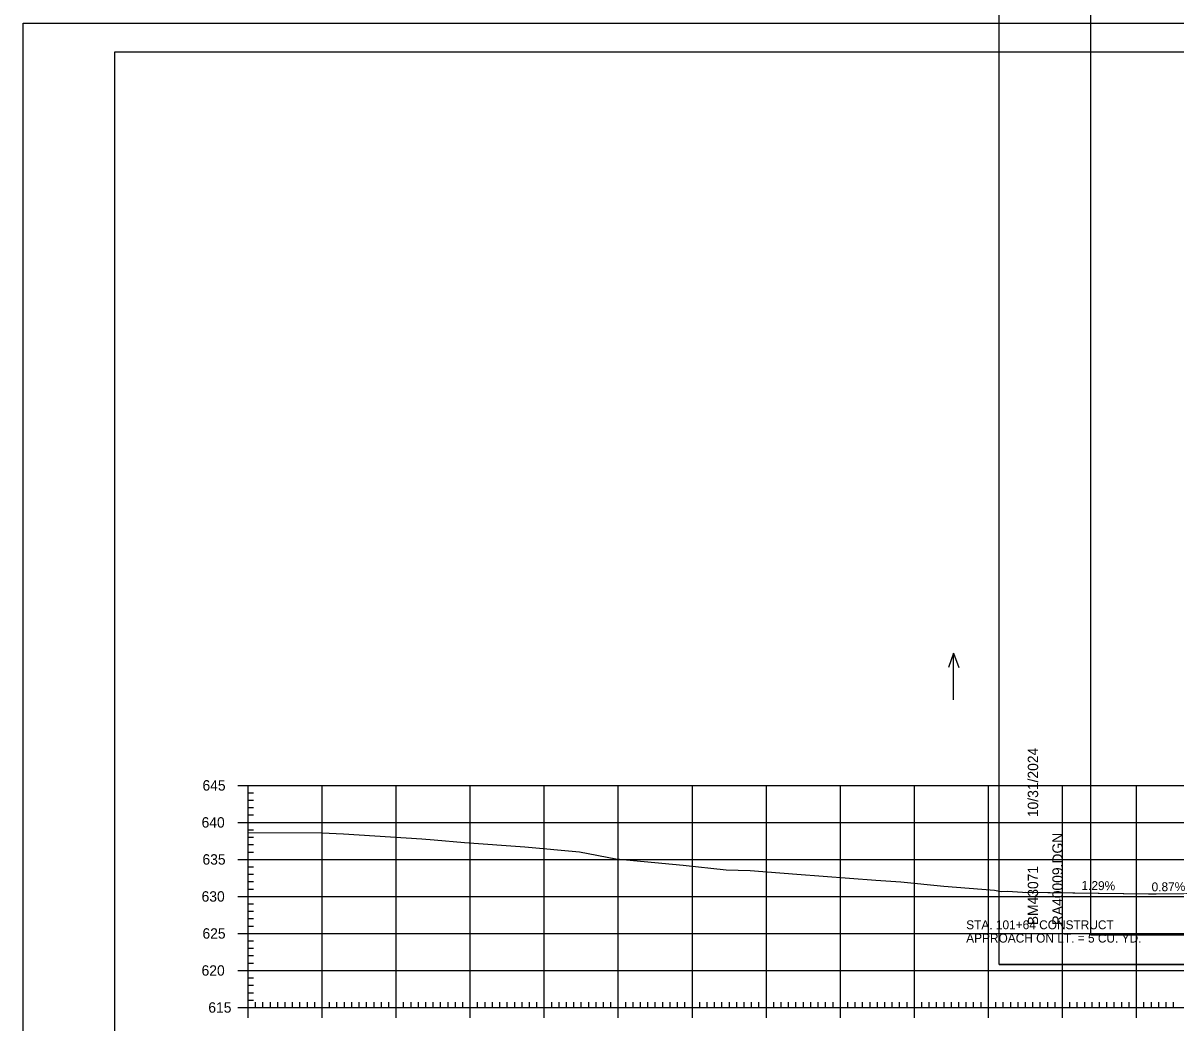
# Model space of a CAD drawing. Extents: x 1381471 to 1382703, y 370300 to 371487.
# Drawn here: x 1381834.4 to 1381990.1, y 370412.6 to 370547.6 of the extents above; entities that cross this region are included whole.
import ezdxf

# ---------------------------------------------------------------- set-up
doc = ezdxf.new("R2010")
doc.units = 0
for name, color, linetype in [('Level 16', 7, 'Continuous'), ('Level 18', 7, 'Continuous'), ('Level 22', 7, 'Continuous'), ('Level 26', 7, 'Continuous'), ('Level 4', 7, 'Continuous'), ('Level 40', 7, 'Continuous'), ('Level 41', 7, 'Continuous'), ('Level 44', 7, 'Continuous'), ('Level 45', 7, 'Continuous'), ('Level 5', 7, 'Continuous'), ('Level 6', 7, 'Continuous')]:
    doc.layers.add(name, color=color, linetype=linetype)

msp = doc.modelspace()

# ---------------------------------------------------------------- linework, layer by layer
at = {"layer": 'Level 16'}
msp.add_line((1381969.77, 370430.24), (1381986.4, 370430.03), dxfattribs=at)
msp.add_lwpolyline([(1381986.4, 370430.03), (1381991.53, 370430.07), (1381991.98, 370430.06), (1381992.77, 370430.05)], dxfattribs=at)
at = {"layer": 'Level 18'}
msp.add_lwpolyline([(1381864.77, 370438.29), (1381874.71, 370438.27), (1381877.66, 370438.13), (1381888.24, 370437.46), (1381889.89, 370437.29), (1381893.98, 370436.94), (1381902.13, 370436.35), (1381909.52, 370435.68), (1381914.45, 370434.75), (1381923.51, 370433.88), (1381929.32, 370433.24), (1381932.59, 370433.16), (1381938.87, 370432.68), (1381949.55, 370431.85), (1381952.95, 370431.62), (1381958.75, 370431.05), (1381965.57, 370430.49), (1381966.49, 370430.33), (1381967.36, 370430.35), (1381969.38, 370430.25), (1381986.4, 370430.03), (1381987.11, 370430.02), (1381987.42, 370430.02), (1381991.53, 370430.07)], dxfattribs=at)
at = {"layer": 'Level 22'}
for p, q in [((1381864.77, 370444.66), (1382144.77, 370444.66)), ((1381864.77, 370414.66), (1381864.77, 370444.66)), ((1381874.77, 370414.66), (1381874.77, 370444.66)), ((1381884.77, 370414.66), (1381884.77, 370444.66)), ((1381894.77, 370414.66), (1381894.77, 370444.66)), ((1381904.77, 370414.66), (1381904.77, 370444.66)), ((1381914.77, 370414.66), (1381914.77, 370444.66)), ((1381924.77, 370414.66), (1381924.77, 370444.66)), ((1381934.77, 370414.66), (1381934.77, 370444.66)), ((1381944.77, 370414.66), (1381944.77, 370444.66)), ((1381954.77, 370414.66), (1381954.77, 370444.66)), ((1381964.77, 370414.66), (1381964.77, 370444.66)), ((1381974.77, 370414.66), (1381974.77, 370444.66)), ((1381984.77, 370414.66), (1381984.77, 370444.66)), ((1381864.77, 370439.66), (1382144.77, 370439.66)), ((1381864.77, 370434.66), (1382144.77, 370434.66)), ((1381864.77, 370429.66), (1382144.77, 370429.66)), ((1381864.77, 370424.66), (1382144.77, 370424.66)), ((1381864.77, 370419.66), (1382144.77, 370419.66)), ((1381864.77, 370414.66), (1382144.77, 370414.66))]:
    msp.add_line(p, q, dxfattribs=at)
at = {"layer": 'Level 26'}
msp.add_line((1381834.37, 370547.63), (1382167.7, 370547.63), dxfattribs=at)
for points in [[(1381834.36, 370547.63), (1382167.7, 370547.63), (1382167.7, 370334.29), (1381834.36, 370334.29)], [(1382080.69, 370543.73), (1382100.31, 370543.73), (1382100.31, 370533.85), (1382116.42, 370533.85), (1382139.62, 370533.85), (1382139.62, 370501.18), (1382162.83, 370501.18), (1382162.95, 370338.27), (1381846.77, 370338.27), (1381846.77, 370543.73)]]:
    msp.add_lwpolyline(points, close=True, dxfattribs=at)
at = {"layer": 'Level 4'}
for p, q in [((1381863.37, 370444.66), (1381866.17, 370444.66)), ((1381864.77, 370414.66), (1381864.77, 370444.66)), ((1381864.77, 370443.66), (1381865.47, 370443.66)), ((1381864.77, 370442.66), (1381865.47, 370442.66)), ((1381864.77, 370441.66), (1381865.47, 370441.66)), ((1381864.77, 370440.66), (1381865.47, 370440.66)), ((1381863.37, 370439.66), (1381866.17, 370439.66)), ((1381864.77, 370438.66), (1381865.47, 370438.66)), ((1381864.77, 370437.66), (1381865.47, 370437.66)), ((1381864.77, 370436.66), (1381865.47, 370436.66)), ((1381863.37, 370434.66), (1381866.17, 370434.66)), ((1381864.77, 370435.66), (1381865.47, 370435.66)), ((1381864.77, 370433.66), (1381865.47, 370433.66)), ((1381864.77, 370432.66), (1381865.47, 370432.66)), ((1381864.77, 370431.66), (1381865.47, 370431.66)), ((1381863.37, 370429.66), (1381866.17, 370429.66)), ((1381864.77, 370430.66), (1381865.47, 370430.66)), ((1381864.77, 370428.66), (1381865.47, 370428.66)), ((1381864.77, 370427.66), (1381865.47, 370427.66)), ((1381864.77, 370426.66), (1381865.47, 370426.66)), ((1381864.77, 370425.66), (1381865.47, 370425.66)), ((1381863.37, 370424.66), (1381866.17, 370424.66)), ((1381864.77, 370423.66), (1381865.47, 370423.66)), ((1381864.77, 370422.66), (1381865.47, 370422.66)), ((1381864.77, 370421.66), (1381865.47, 370421.66)), ((1381864.77, 370420.66), (1381865.47, 370420.66)), ((1381863.37, 370419.66), (1381866.17, 370419.66)), ((1381864.77, 370418.66), (1381865.47, 370418.66)), ((1381864.77, 370417.66), (1381865.47, 370417.66)), ((1381864.77, 370416.66), (1381865.47, 370416.66)), ((1381864.77, 370413.26), (1381864.77, 370416.06)), ((1381864.77, 370415.66), (1381865.47, 370415.66)), ((1381874.77, 370413.26), (1381874.77, 370416.06)), ((1381884.77, 370413.26), (1381884.77, 370416.06)), ((1381894.77, 370413.26), (1381894.77, 370416.06)), ((1381904.77, 370413.26), (1381904.77, 370416.06)), ((1381914.77, 370413.26), (1381914.77, 370416.06)), ((1381924.77, 370413.26), (1381924.77, 370416.06)), ((1381934.77, 370413.26), (1381934.77, 370416.06)), ((1381944.77, 370413.26), (1381944.77, 370416.06)), ((1381954.77, 370413.26), (1381954.77, 370416.06)), ((1381964.77, 370413.26), (1381964.77, 370416.06)), ((1381974.77, 370413.26), (1381974.77, 370416.06)), ((1381984.77, 370413.26), (1381984.77, 370416.06)), ((1381863.37, 370414.66), (1381866.17, 370414.66)), ((1381864.77, 370414.66), (1382144.77, 370414.66)), ((1381865.77, 370414.66), (1381865.77, 370415.36)), ((1381866.77, 370414.66), (1381866.77, 370415.36)), ((1381867.77, 370414.66), (1381867.77, 370415.36)), ((1381868.77, 370414.66), (1381868.77, 370415.36)), ((1381869.77, 370414.66), (1381869.77, 370415.36)), ((1381870.77, 370414.66), (1381870.77, 370415.36)), ((1381871.77, 370414.66), (1381871.77, 370415.36)), ((1381872.77, 370414.66), (1381872.77, 370415.36)), ((1381873.77, 370414.66), (1381873.77, 370415.36)), ((1381875.77, 370414.66), (1381875.77, 370415.36)), ((1381876.77, 370414.66), (1381876.77, 370415.36)), ((1381877.77, 370414.66), (1381877.77, 370415.36)), ((1381878.77, 370414.66), (1381878.77, 370415.36)), ((1381879.77, 370414.66), (1381879.77, 370415.36)), ((1381880.77, 370414.66), (1381880.77, 370415.36)), ((1381881.77, 370414.66), (1381881.77, 370415.36)), ((1381882.77, 370414.66), (1381882.77, 370415.36)), ((1381883.77, 370414.66), (1381883.77, 370415.36)), ((1381885.77, 370414.66), (1381885.77, 370415.36)), ((1381886.77, 370414.66), (1381886.77, 370415.36)), ((1381887.77, 370414.66), (1381887.77, 370415.36)), ((1381888.77, 370414.66), (1381888.77, 370415.36)), ((1381889.77, 370414.66), (1381889.77, 370415.36)), ((1381890.77, 370414.66), (1381890.77, 370415.36)), ((1381891.77, 370414.66), (1381891.77, 370415.36)), ((1381892.77, 370414.66), (1381892.77, 370415.36)), ((1381893.77, 370414.66), (1381893.77, 370415.36)), ((1381895.77, 370414.66), (1381895.77, 370415.36)), ((1381896.77, 370414.66), (1381896.77, 370415.36)), ((1381897.77, 370414.66), (1381897.77, 370415.36)), ((1381898.77, 370414.66), (1381898.77, 370415.36)), ((1381899.77, 370414.66), (1381899.77, 370415.36)), ((1381900.77, 370414.66), (1381900.77, 370415.36)), ((1381901.77, 370414.66), (1381901.77, 370415.36)), ((1381902.77, 370414.66), (1381902.77, 370415.36)), ((1381903.77, 370414.66), (1381903.77, 370415.36)), ((1381905.77, 370414.66), (1381905.77, 370415.36)), ((1381906.77, 370414.66), (1381906.77, 370415.36)), ((1381907.77, 370414.66), (1381907.77, 370415.36)), ((1381908.77, 370414.66), (1381908.77, 370415.36)), ((1381909.77, 370414.66), (1381909.77, 370415.36)), ((1381910.77, 370414.66), (1381910.77, 370415.36)), ((1381911.77, 370414.66), (1381911.77, 370415.36)), ((1381912.77, 370414.66), (1381912.77, 370415.36)), ((1381913.77, 370414.66), (1381913.77, 370415.36)), ((1381915.77, 370414.66), (1381915.77, 370415.36)), ((1381916.77, 370414.66), (1381916.77, 370415.36)), ((1381917.77, 370414.66), (1381917.77, 370415.36)), ((1381918.77, 370414.66), (1381918.77, 370415.36)), ((1381919.77, 370414.66), (1381919.77, 370415.36)), ((1381920.77, 370414.66), (1381920.77, 370415.36)), ((1381921.77, 370414.66), (1381921.77, 370415.36)), ((1381922.77, 370414.66), (1381922.77, 370415.36)), ((1381923.77, 370414.66), (1381923.77, 370415.36)), ((1381925.77, 370414.66), (1381925.77, 370415.36)), ((1381926.77, 370414.66), (1381926.77, 370415.36)), ((1381927.77, 370414.66), (1381927.77, 370415.36)), ((1381928.77, 370414.66), (1381928.77, 370415.36)), ((1381929.77, 370414.66), (1381929.77, 370415.36)), ((1381930.77, 370414.66), (1381930.77, 370415.36)), ((1381931.77, 370414.66), (1381931.77, 370415.36)), ((1381932.77, 370414.66), (1381932.77, 370415.36)), ((1381933.77, 370414.66), (1381933.77, 370415.36)), ((1381935.77, 370414.66), (1381935.77, 370415.36)), ((1381936.77, 370414.66), (1381936.77, 370415.36)), ((1381937.77, 370414.66), (1381937.77, 370415.36)), ((1381938.77, 370414.66), (1381938.77, 370415.36)), ((1381939.77, 370414.66), (1381939.77, 370415.36)), ((1381940.77, 370414.66), (1381940.77, 370415.36)), ((1381941.77, 370414.66), (1381941.77, 370415.36)), ((1381942.77, 370414.66), (1381942.77, 370415.36)), ((1381943.77, 370414.66), (1381943.77, 370415.36)), ((1381945.77, 370414.66), (1381945.77, 370415.36)), ((1381946.77, 370414.66), (1381946.77, 370415.36)), ((1381947.77, 370414.66), (1381947.77, 370415.36)), ((1381948.77, 370414.66), (1381948.77, 370415.36)), ((1381949.77, 370414.66), (1381949.77, 370415.36)), ((1381950.77, 370414.66), (1381950.77, 370415.36)), ((1381951.77, 370414.66), (1381951.77, 370415.36)), ((1381952.77, 370414.66), (1381952.77, 370415.36)), ((1381953.77, 370414.66), (1381953.77, 370415.36)), ((1381955.77, 370414.66), (1381955.77, 370415.36)), ((1381956.77, 370414.66), (1381956.77, 370415.36)), ((1381957.77, 370414.66), (1381957.77, 370415.36)), ((1381958.77, 370414.66), (1381958.77, 370415.36)), ((1381959.77, 370414.66), (1381959.77, 370415.36)), ((1381960.77, 370414.66), (1381960.77, 370415.36)), ((1381961.77, 370414.66), (1381961.77, 370415.36)), ((1381962.77, 370414.66), (1381962.77, 370415.36)), ((1381963.77, 370414.66), (1381963.77, 370415.36)), ((1381965.77, 370414.66), (1381965.77, 370415.36)), ((1381966.77, 370414.66), (1381966.77, 370415.36)), ((1381967.77, 370414.66), (1381967.77, 370415.36)), ((1381968.77, 370414.66), (1381968.77, 370415.36)), ((1381969.77, 370414.66), (1381969.77, 370415.36)), ((1381970.77, 370414.66), (1381970.77, 370415.36)), ((1381971.77, 370414.66), (1381971.77, 370415.36)), ((1381972.77, 370414.66), (1381972.77, 370415.36)), ((1381973.77, 370414.66), (1381973.77, 370415.36)), ((1381975.77, 370414.66), (1381975.77, 370415.36)), ((1381976.77, 370414.66), (1381976.77, 370415.36)), ((1381977.77, 370414.66), (1381977.77, 370415.36)), ((1381978.77, 370414.66), (1381978.77, 370415.36)), ((1381979.77, 370414.66), (1381979.77, 370415.36)), ((1381980.77, 370414.66), (1381980.77, 370415.36)), ((1381981.77, 370414.66), (1381981.77, 370415.36)), ((1381982.77, 370414.66), (1381982.77, 370415.36)), ((1381983.77, 370414.66), (1381983.77, 370415.36)), ((1381985.77, 370414.66), (1381985.77, 370415.36)), ((1381986.77, 370414.66), (1381986.77, 370415.36)), ((1381987.77, 370414.66), (1381987.77, 370415.36)), ((1381988.77, 370414.66), (1381988.77, 370415.36)), ((1381989.77, 370414.66), (1381989.77, 370415.36))]:
    msp.add_line(p, q, dxfattribs=at)
at = {"layer": 'Level 40'}
for p, q in [((1381960.05, 370462.51), (1381959.35, 370460.59)), ((1381960.05, 370456.23), (1381960.05, 370462.51)), ((1381960.05, 370462.51), (1381960.75, 370460.59))]:
    msp.add_line(p, q, dxfattribs=at)
at = {"layer": 'Level 45'}
for p, q in [((1381978.61, 370424.44), (1381978.61, 370629.9)), ((1381978.61, 370424.44), (1381978.61, 370424.44)), ((1382294.79, 370424.44), (1381978.61, 370424.44)), ((1381966.21, 370420.47), (1382299.55, 370420.47))]:
    msp.add_line(p, q, dxfattribs=at)
for points in [[(1381966.21, 370633.8), (1382299.55, 370633.8), (1382299.55, 370420.46), (1381966.21, 370420.46)], [(1382212.53, 370629.9), (1382232.15, 370629.9), (1382232.15, 370620.02), (1382248.27, 370620.02), (1382271.46, 370620.02), (1382271.46, 370595.69), (1382294.79, 370595.69), (1382294.79, 370424.44), (1381978.61, 370424.44), (1381978.61, 370629.9)]]:
    msp.add_lwpolyline(points, close=True, dxfattribs=at)
at = {"layer": 'Level 6'}
for p, q in [((1381846.77, 370543.73), (1382162.95, 370543.73)), ((1381846.77, 370338.27), (1381846.77, 370543.73))]:
    msp.add_line(p, q, dxfattribs=at)

# ---------------------------------------------------------------- texts
at = {"layer": 'Level 41'}
for s, rotation, p in [('1.29%', 359.2581, (1381977.33, 370430.55)), ('0.87%', 0.4984, (1381986.81, 370430.35))]:
    msp.add_text(s, height=1.2, rotation=rotation, dxfattribs=at).set_placement(p)
at = {"layer": 'Level 44'}
for s, p in [('STA. 101+64 CONSTRUCT', (1381961.76, 370425.23)), ('APPROACH ON LT. = 5 CU. YD.', (1381961.76, 370423.43))]:
    msp.add_text(s, height=1.2, dxfattribs=at).set_placement(p)
at = {"layer": 'Level 45'}
for s, p in [('10/31/2024', (1381971.48, 370440.37)), ('RA40009.DGN', (1381974.8, 370425.77)), ('BM43071', (1381971.48, 370425.77))]:
    msp.add_text(s, height=1.4, rotation=90, dxfattribs=at).set_placement(p)
at = {"layer": 'Level 5'}
for s, p in [('645', (1381858.6, 370443.96)), ('640', (1381858.48, 370438.96)), ('635', (1381858.6, 370433.96)), ('630', (1381858.48, 370428.96)), ('625', (1381858.6, 370423.96)), ('620', (1381858.48, 370418.96)), ('615', (1381859.39, 370413.96))]:
    msp.add_text(s, height=1.4, dxfattribs=at).set_placement(p)

doc.saveas('drawing.dxf')
